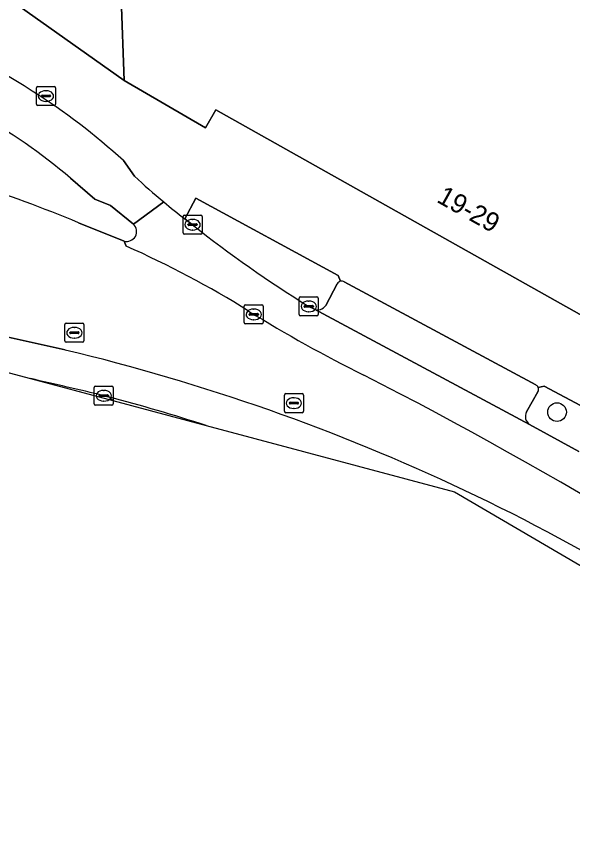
# Model space of a CAD drawing. Extents: x 161771 to 163125, y 382475 to 383179.
# Drawn here: x 161909.43 to 161938.58, y 382804.07 to 382847.18 of the extents above; entities that cross this region are included whole.
import ezdxf

# ---------------------------------------------------------------- set-up
doc = ezdxf.new("R2010")
doc.units = 0
for name, color, linetype in [('IMGEO_Boom', 7, 'Continuous'), ('IMGEO_Fietspad_gesloten', 7, 'Continuous'), ('IMGEO_Groenvoorziening', 7, 'Continuous'), ('IMGEO_Kolk', 7, 'Continuous'), ('IMGEO_Pand', 7, 'Continuous'), ('IMGEO_Pand_nummerreeks', 7, 'Continuous'), ('IMGEO_Parkeervlak_open', 7, 'Continuous'), ('IMGEO_Rijbaan_lokaal_gesloten', 7, 'Continuous'), ('IMGEO_Rijbaan_lokaal_open', 7, 'Continuous'), ('IMGEO_Rioolput', 7, 'Continuous'), ('IMGEO_Verkeerseiland_open', 7, 'Continuous'), ('IMGEO_Voetpad_open', 7, 'Continuous')]:
    doc.layers.add(name, color=color, linetype=linetype)

msp = doc.modelspace()

# ---------------------------------------------------------------- linework, layer by layer
at = {"layer": 'IMGEO_Boom'}
msp.add_circle((161937.763, 382826.46), 0.489, dxfattribs=at)
at = {"layer": 'IMGEO_Fietspad_gesloten'}
for points in [[(161915.615, 382838.816), (161915.031, 382839.631)], [(161912.258, 382838.707), (161913.543, 382837.611), (161914.36, 382837.276), (161915.553, 382836.298), (161917.147, 382837.468)]]:
    msp.add_lwpolyline(points, dxfattribs=at)
for centre, radius, start, end in [((161893.52, 382817.587), 30.654, 56.9204, 72.0344), ((161892.387, 382814.862), 33.56, 47.5667, 57.8391), ((161893.478, 382816.788), 28.864, 49.4108, 61.3259), ((161941.936, 382867.185), 38.699, 227.1448, 230.1664)]:
    msp.add_arc(centre, radius, start, end, dxfattribs=at)
at = {"layer": 'IMGEO_Groenvoorziening'}
for points in [[(161926.413, 382833.312), (161926.289, 382833.608), (161918.824, 382837.659), (161918.256, 382836.578)], [(161918.256, 382836.578), (161918.66, 382836.276)], [(161925.636, 382832.046), (161926.245, 382833.185)], [(161924.749, 382831.998), (161925.01, 382831.862)], [(161940.409, 382825.753), (161940.331, 382826.089), (161937.087, 382827.816), (161936.776, 382827.755)], [(161936.764, 382827.519), (161936.155, 382826.469)], [(161936.32, 382825.81), (161938.902, 382824.399)]]:
    msp.add_lwpolyline(points, dxfattribs=at)
for centre, radius, start, end in [((161956.208, 382883.247), 60.134, 231.36149, 238.45641), ((161926.482, 382833.046), 0.274, 104.5285, 149.6466), ((161925.219, 382832.307), 0.492, 244.8527, 327.9066), ((161936.525, 382827.649), 0.272, 331.33, 22.8483), ((161936.635, 382826.239), 0.532, 154.3803, 233.7331)]:
    msp.add_arc(centre, radius, start, end, dxfattribs=at)
at = {"layer": 'IMGEO_Kolk'}
for p, q in [((161910.471, 382842.589), (161910.471, 382843.441)), ((161910.546, 382843.515), (161911.398, 382843.515)), ((161910.959, 382843.295), (161910.984, 382843.295)), ((161911.472, 382843.441), (161911.472, 382842.589)), ((161910.73, 382843.009), (161910.73, 382843.021)), ((161911.168, 382842.972), (161910.77, 382842.972)), ((161910.773, 382843.058), (161911.171, 382843.058)), ((161910.982, 382842.735), (161910.957, 382842.735)), ((161911.214, 382843.021), (161911.214, 382843.009)), ((161911.398, 382842.515), (161910.546, 382842.515)), ((161918.159, 382835.85), (161918.159, 382836.702)), ((161918.234, 382836.776), (161919.086, 382836.776)), ((161919.16, 382836.702), (161919.16, 382835.85)), ((161918.418, 382836.27), (161918.418, 382836.282)), ((161918.856, 382836.233), (161918.458, 382836.233)), ((161918.461, 382836.319), (161918.859, 382836.319)), ((161918.647, 382836.556), (161918.672, 382836.556)), ((161918.902, 382836.282), (161918.902, 382836.27)), ((161918.67, 382835.996), (161918.645, 382835.996)), ((161919.086, 382835.776), (161918.234, 382835.776)), ((161924.248, 382831.572), (161924.248, 382832.424)), ((161924.323, 382832.498), (161925.175, 382832.498)), ((161925.249, 382832.424), (161925.249, 382831.572)), ((161924.507, 382831.992), (161924.507, 382832.004)), ((161924.945, 382831.955), (161924.547, 382831.955)), ((161924.55, 382832.041), (161924.948, 382832.041)), ((161924.736, 382832.278), (161924.761, 382832.278)), ((161924.991, 382832.004), (161924.991, 382831.992)), ((161925.175, 382831.498), (161924.323, 382831.498)), ((161924.759, 382831.718), (161924.734, 382831.718)), ((161913.502, 382826.893), (161913.502, 382827.745)), ((161913.577, 382827.819), (161914.429, 382827.819)), ((161913.99, 382827.599), (161914.015, 382827.599)), ((161914.503, 382827.745), (161914.503, 382826.893)), ((161913.761, 382827.313), (161913.761, 382827.325)), ((161914.199, 382827.276), (161913.801, 382827.276)), ((161913.804, 382827.362), (161914.202, 382827.362)), ((161914.245, 382827.325), (161914.245, 382827.313)), ((161914.429, 382826.819), (161913.577, 382826.819)), ((161914.013, 382827.039), (161913.988, 382827.039))]:
    msp.add_line(p, q, dxfattribs=at)
for points in [[(161910.471, 382842.589), (161910.471, 382843.441)], [(161910.546, 382843.515), (161911.398, 382843.515)], [(161911.472, 382843.441), (161911.472, 382842.589)], [(161911.398, 382842.515), (161910.546, 382842.515)], [(161918.159, 382835.85), (161918.159, 382836.702)], [(161918.234, 382836.776), (161919.086, 382836.776)], [(161919.16, 382836.702), (161919.16, 382835.85)], [(161919.086, 382835.776), (161918.234, 382835.776)], [(161924.248, 382831.572), (161924.248, 382832.424)], [(161924.323, 382832.498), (161925.175, 382832.498)], [(161925.249, 382832.424), (161925.249, 382831.572)], [(161925.175, 382831.498), (161924.323, 382831.498)], [(161913.502, 382826.893), (161913.502, 382827.745)], [(161913.577, 382827.819), (161914.429, 382827.819)], [(161914.503, 382827.745), (161914.503, 382826.893)], [(161914.429, 382826.819), (161913.577, 382826.819)]]:
    msp.add_lwpolyline(points, dxfattribs=at)
for centre, radius, start, end in [((161910.548, 382843.439), 0.0765, 91.552, 178.448), ((161910.548, 382843.439), 0.0765, 91.552, 178.448), ((161911.396, 382843.439), 0.0765, 1.552, 88.448), ((161911.396, 382843.439), 0.0765, 1.552, 88.448), ((161910.77, 382843.018), 0.0403, 85.8775, 175.7526), ((161910.767, 382843.008), 0.0366, 178.938, 274.7102), ((161911.171, 382843.015), 0.043, 264.8664, 352.4533), ((161911.175, 382843.02), 0.0386, 1.7309, 96.639), ((161910.548, 382842.591), 0.0765, 181.552, 268.448), ((161910.548, 382842.591), 0.0765, 181.552, 268.448), ((161911.396, 382842.591), 0.0765, 271.552, 358.448), ((161911.396, 382842.591), 0.0765, 271.552, 358.448), ((161918.236, 382836.7), 0.0765, 91.552, 178.448), ((161918.236, 382836.7), 0.0765, 91.552, 178.448), ((161919.084, 382836.7), 0.0765, 1.552, 88.448), ((161919.084, 382836.7), 0.0765, 1.552, 88.448), ((161918.458, 382836.279), 0.0403, 85.8775, 175.7526), ((161918.455, 382836.269), 0.0366, 178.938, 274.7102), ((161918.859, 382836.276), 0.043, 264.8664, 352.4533), ((161918.863, 382836.281), 0.0386, 1.7309, 96.639), ((161918.236, 382835.852), 0.0765, 181.552, 268.448), ((161918.236, 382835.852), 0.0765, 181.552, 268.448), ((161919.084, 382835.852), 0.0765, 271.552, 358.448), ((161919.084, 382835.852), 0.0765, 271.552, 358.448), ((161924.325, 382832.422), 0.0765, 91.552, 178.448), ((161924.325, 382832.422), 0.0765, 91.552, 178.448), ((161925.173, 382832.422), 0.0765, 1.552, 88.448), ((161925.173, 382832.422), 0.0765, 1.552, 88.448), ((161924.547, 382832.001), 0.0403, 85.8775, 175.7526), ((161924.544, 382831.991), 0.0366, 178.938, 274.7102), ((161924.948, 382831.998), 0.043, 264.8664, 352.4533), ((161924.952, 382832.003), 0.0386, 1.7309, 96.639), ((161924.325, 382831.574), 0.0765, 181.552, 268.448), ((161924.325, 382831.574), 0.0765, 181.552, 268.448), ((161925.173, 382831.574), 0.0765, 271.552, 358.448), ((161925.173, 382831.574), 0.0765, 271.552, 358.448), ((161913.579, 382827.743), 0.0765, 91.552, 178.448), ((161913.579, 382827.743), 0.0765, 91.552, 178.448), ((161914.427, 382827.743), 0.0765, 1.552, 88.448), ((161914.427, 382827.743), 0.0765, 1.552, 88.448), ((161913.801, 382827.322), 0.0403, 85.8775, 175.7526), ((161913.798, 382827.312), 0.0366, 178.938, 274.7102), ((161914.202, 382827.319), 0.043, 264.8664, 352.4533), ((161914.206, 382827.324), 0.0386, 1.7309, 96.639), ((161913.579, 382826.895), 0.0765, 181.552, 268.448), ((161913.579, 382826.895), 0.0765, 181.552, 268.448), ((161914.427, 382826.895), 0.0765, 271.552, 358.448), ((161914.427, 382826.895), 0.0765, 271.552, 358.448)]:
    msp.add_arc(centre, radius, start, end, dxfattribs=at)
for centre, major_axis, ratio, start_param, end_param in [((161910.958, 382843.015), (-0.387, 0.002), 0.722429, 4.712389, 7.853982), ((161910.983, 382843.015), (-0.39, 0.002), 0.717154, 1.570796, 4.712389), ((161918.646, 382836.276), (-0.387, 0.002), 0.722429, 4.712389, 7.853982), ((161918.671, 382836.276), (-0.39, 0.002), 0.717154, 1.570796, 4.712389), ((161924.735, 382831.998), (-0.387, 0.002), 0.722429, 4.712389, 7.853982), ((161924.76, 382831.998), (-0.39, 0.002), 0.717154, 1.570796, 4.712389), ((161913.989, 382827.319), (-0.387, 0.002), 0.722429, 4.712389, 7.853982), ((161914.014, 382827.319), (-0.39, 0.002), 0.717154, 1.570796, 4.712389)]:
    msp.add_ellipse(centre, major_axis=major_axis, ratio=ratio, start_param=start_param, end_param=end_param, dxfattribs=at)
at = {"layer": 'IMGEO_Pand'}
msp.add_lwpolyline([(161938.172, 382855.87), (161935.571, 382851.327), (161925.788, 382856.766), (161923.225, 382854.706), (161921.507, 382853.326), (161918.6, 382851.014), (161914.919, 382848.172), (161915.064, 382843.832), (161919.34, 382841.346), (161919.878, 382842.285), (161944.451, 382828.498), (161949.455, 382837.351), (161954.479, 382841.299), (161958.508, 382844.465)], close=True, dxfattribs=at)
at = {"layer": 'IMGEO_Parkeervlak_open'}
for points in [[(161936.655, 382827.886), (161926.611, 382833.288)], [(161926.245, 382833.185), (161925.636, 382832.046)], [(161925.01, 382831.862), (161936.32, 382825.81)], [(161936.155, 382826.469), (161936.764, 382827.519)], [(161914.482, 382827.063), (161919.366, 382825.762)]]:
    msp.add_lwpolyline(points, dxfattribs=at)
for centre, radius, start, end in [((161926.482, 382833.046), 0.274, 104.5285, 149.6466), ((161926.482, 382833.051), 0.27, 61.4009, 104.7767), ((161925.219, 382832.307), 0.492, 244.8527, 327.9066), ((161936.534, 382827.653), 0.263, 22.9147, 62.5404), ((161936.525, 382827.649), 0.272, 331.33, 22.8483), ((161889.903, 382734.077), 96.303, 72.18528, 75.35985), ((161914.05, 382826.763), 0.527, 34.7532, 68.4794), ((161936.635, 382826.239), 0.532, 154.3803, 233.7331)]:
    msp.add_arc(centre, radius, start, end, dxfattribs=at)
at = {"layer": 'IMGEO_Rijbaan_lokaal_gesloten'}
for points in [[(161917.147, 382837.468), (161915.553, 382836.298)], [(161918.66, 382836.276), (161918.256, 382836.578)], [(161915.067, 382835.419), (161915.18, 382835.151)], [(161911.985, 382829.713), (161908.827, 382830.418), (161897.919, 382832.611), (161894.604, 382833.278), (161894.438, 382831.588), (161898.722, 382831.263), (161910.159, 382828.215)], [(161938.902, 382824.399), (161936.32, 382825.81), (161925.01, 382831.862), (161924.749, 382831.998)], [(161914.003, 382827.319), (161914.243, 382827.253)], [(161919.366, 382825.762), (161932.388, 382822.292), (161951.892, 382810.876)]]:
    msp.add_lwpolyline(points, dxfattribs=at)
for centre, radius, start, end in [((161941.254, 382866.371), 37.637, 230.1697, 232.3345), ((161915.208, 382835.915), 0.515, 254.091, 48.0325), ((161956.208, 382883.247), 60.134, 231.36149, 238.45641), ((161894.407, 382788.165), 51.373, 58.0449, 66.1499), ((161959.575, 382893.012), 72.076, 238.20251, 243.6899), ((161886.934, 382724.948), 107.718, 52.91192, 76.55194), ((161858.06, 382596.106), 237.884, 76.39844, 77.34917), ((161822.897, 382623.343), 230.256, 54.43143, 62.94481), ((161889.903, 382734.077), 96.303, 72.18528, 75.35985)]:
    msp.add_arc(centre, radius, start, end, dxfattribs=at)
at = {"layer": 'IMGEO_Rijbaan_lokaal_open'}
for points in [[(161915.18, 382835.151), (161915.067, 382835.419), (161912.674, 382836.378)], [(161908.124, 382832.781), (161898.168, 382834.829), (161897.919, 382832.611), (161908.827, 382830.418), (161911.985, 382829.713)]]:
    msp.add_lwpolyline(points, dxfattribs=at)
for centre, radius, start, end in [((161884.089, 382767.932), 74.175, 67.33298, 76.62355), ((161894.407, 382788.165), 51.373, 58.0449, 66.1499), ((161959.575, 382893.012), 72.076, 238.20251, 243.6899), ((161886.934, 382724.948), 107.718, 52.91192, 76.55194), ((161822.897, 382623.343), 230.256, 54.43143, 62.94481)]:
    msp.add_arc(centre, radius, start, end, dxfattribs=at)
at = {"layer": 'IMGEO_Rioolput'}
for p, q in [((161921.363, 382831.152), (161921.363, 382832.004)), ((161921.438, 382832.078), (161922.29, 382832.078)), ((161922.364, 382832.004), (161922.364, 382831.152)), ((161921.622, 382831.572), (161921.622, 382831.584)), ((161922.06, 382831.535), (161921.662, 382831.535)), ((161921.665, 382831.621), (161922.063, 382831.621)), ((161921.851, 382831.858), (161921.876, 382831.858)), ((161922.106, 382831.584), (161922.106, 382831.572)), ((161911.961, 382830.19), (161911.961, 382831.042)), ((161912.036, 382831.116), (161912.888, 382831.116)), ((161912.962, 382831.042), (161912.962, 382830.19)), ((161922.29, 382831.078), (161921.438, 382831.078)), ((161921.874, 382831.298), (161921.849, 382831.298)), ((161912.22, 382830.61), (161912.22, 382830.622)), ((161912.263, 382830.659), (161912.661, 382830.659)), ((161912.449, 382830.896), (161912.474, 382830.896)), ((161912.704, 382830.622), (161912.704, 382830.61)), ((161912.658, 382830.573), (161912.26, 382830.573)), ((161912.472, 382830.336), (161912.447, 382830.336)), ((161912.888, 382830.116), (161912.036, 382830.116)), ((161923.47, 382826.503), (161923.47, 382827.355)), ((161923.545, 382827.429), (161924.397, 382827.429)), ((161923.958, 382827.209), (161923.983, 382827.209)), ((161924.471, 382827.355), (161924.471, 382826.503)), ((161923.729, 382826.923), (161923.729, 382826.935)), ((161924.167, 382826.886), (161923.769, 382826.886)), ((161923.772, 382826.972), (161924.17, 382826.972)), ((161924.213, 382826.935), (161924.213, 382826.923)), ((161924.397, 382826.429), (161923.545, 382826.429)), ((161923.981, 382826.649), (161923.956, 382826.649))]:
    msp.add_line(p, q, dxfattribs=at)
for points in [[(161921.363, 382831.152), (161921.363, 382832.004)], [(161921.438, 382832.078), (161922.29, 382832.078)], [(161922.364, 382832.004), (161922.364, 382831.152)], [(161911.961, 382830.19), (161911.961, 382831.042)], [(161912.036, 382831.116), (161912.888, 382831.116)], [(161912.962, 382831.042), (161912.962, 382830.19)], [(161922.29, 382831.078), (161921.438, 382831.078)], [(161912.888, 382830.116), (161912.036, 382830.116)], [(161923.47, 382826.503), (161923.47, 382827.355)], [(161923.545, 382827.429), (161924.397, 382827.429)], [(161924.471, 382827.355), (161924.471, 382826.503)], [(161924.397, 382826.429), (161923.545, 382826.429)]]:
    msp.add_lwpolyline(points, dxfattribs=at)
for centre, radius, start, end in [((161921.44, 382832.002), 0.0765, 91.552, 178.448), ((161921.44, 382832.002), 0.0765, 91.552, 178.448), ((161922.288, 382832.002), 0.0765, 1.552, 88.448), ((161922.288, 382832.002), 0.0765, 1.552, 88.448), ((161921.662, 382831.581), 0.0403, 85.8775, 175.7526), ((161921.659, 382831.571), 0.0366, 178.938, 274.7102), ((161922.063, 382831.578), 0.043, 264.8664, 352.4533), ((161922.067, 382831.583), 0.0386, 1.7309, 96.639), ((161912.038, 382831.04), 0.0765, 91.552, 178.448), ((161912.038, 382831.04), 0.0765, 91.552, 178.448), ((161912.886, 382831.04), 0.0765, 1.552, 88.448), ((161912.886, 382831.04), 0.0765, 1.552, 88.448), ((161921.44, 382831.154), 0.0765, 181.552, 268.448), ((161921.44, 382831.154), 0.0765, 181.552, 268.448), ((161922.288, 382831.154), 0.0765, 271.552, 358.448), ((161922.288, 382831.154), 0.0765, 271.552, 358.448), ((161912.26, 382830.619), 0.0403, 85.8775, 175.7526), ((161912.257, 382830.609), 0.0366, 178.938, 274.7102), ((161912.661, 382830.616), 0.043, 264.8664, 352.4533), ((161912.665, 382830.621), 0.0386, 1.7309, 96.639), ((161912.038, 382830.192), 0.0765, 181.552, 268.448), ((161912.038, 382830.192), 0.0765, 181.552, 268.448), ((161912.886, 382830.192), 0.0765, 271.552, 358.448), ((161912.886, 382830.192), 0.0765, 271.552, 358.448), ((161923.547, 382827.353), 0.0765, 91.552, 178.448), ((161923.547, 382827.353), 0.0765, 91.552, 178.448), ((161924.395, 382827.353), 0.0765, 1.552, 88.448), ((161924.395, 382827.353), 0.0765, 1.552, 88.448), ((161923.769, 382826.932), 0.0403, 85.8775, 175.7526), ((161923.766, 382826.922), 0.0366, 178.938, 274.7102), ((161924.17, 382826.929), 0.043, 264.8664, 352.4533), ((161924.174, 382826.934), 0.0386, 1.7309, 96.639), ((161923.547, 382826.505), 0.0765, 181.552, 268.448), ((161923.547, 382826.505), 0.0765, 181.552, 268.448), ((161924.395, 382826.505), 0.0765, 271.552, 358.448), ((161924.395, 382826.505), 0.0765, 271.552, 358.448)]:
    msp.add_arc(centre, radius, start, end, dxfattribs=at)
for centre, major_axis, ratio, start_param, end_param in [((161921.85, 382831.578), (-0.387, 0.002), 0.722429, 4.712389, 7.853982), ((161921.875, 382831.578), (-0.39, 0.002), 0.717154, 1.570796, 4.712389), ((161912.448, 382830.616), (-0.387, 0.002), 0.722429, 4.712389, 7.853982), ((161912.473, 382830.616), (-0.39, 0.002), 0.717154, 1.570796, 4.712389), ((161923.957, 382826.929), (-0.387, 0.002), 0.722429, 4.712389, 7.853982), ((161923.982, 382826.929), (-0.39, 0.002), 0.717154, 1.570796, 4.712389)]:
    msp.add_ellipse(centre, major_axis=major_axis, ratio=ratio, start_param=start_param, end_param=end_param, dxfattribs=at)
at = {"layer": 'IMGEO_Verkeerseiland_open'}
for points in [[(161915.553, 382836.298), (161914.36, 382837.276), (161913.543, 382837.611), (161912.258, 382838.707)], [(161912.674, 382836.378), (161915.067, 382835.419)]]:
    msp.add_lwpolyline(points, dxfattribs=at)
for centre, radius, start, end in [((161893.478, 382816.788), 28.864, 49.4108, 61.3259), ((161884.089, 382767.932), 74.175, 67.33298, 76.62355), ((161915.208, 382835.915), 0.515, 254.091, 48.0325)]:
    msp.add_arc(centre, radius, start, end, dxfattribs=at)
at = {"layer": 'IMGEO_Voetpad_open'}
for points in [[(161908.806, 382849.443), (161908.423, 382848.544), (161915.064, 382843.832), (161914.919, 382848.172), (161918.6, 382851.014), (161919.975, 382853.379), (161920.916, 382852.897), (161922.304, 382855.223), (161923.225, 382854.706), (161925.788, 382856.766), (161930.217, 382860.359), (161934.42, 382863.739), (161937.25, 382865.994), (161937.488, 382866.185)], [(161919.878, 382842.285), (161919.34, 382841.346), (161915.064, 382843.832), (161908.423, 382848.544), (161907.047, 382848.97), (161903.828, 382850.026), (161902.529, 382850.444), (161902.759, 382851.432)], [(162013.278, 382773.96), (162016.666, 382777.602), (162014.703, 382779.815), (162012.95, 382779.713), (162008.994, 382783.177), (162008.9, 382783.259), (162007.486, 382781.832), (162003.337, 382785.143), (162000, 382787.854), (161997.776, 382789.66), (161999.165, 382791.37), (161993.375, 382796.093), (161993.267, 382795.96), (161979.452, 382807.183), (161979.326, 382806.979), (161978.893, 382807.245), (161972.332, 382811.265), (161965.52, 382815.44), (161962.509, 382817.293), (161953.171, 382822.43), (161943.963, 382827.66), (161944.451, 382828.498), (161919.878, 382842.285)], [(161915.031, 382839.631), (161915.615, 382838.816)], [(161918.256, 382836.578), (161918.824, 382837.659), (161926.289, 382833.608), (161926.413, 382833.312)], [(161926.611, 382833.288), (161936.655, 382827.886)], [(161910.159, 382828.215), (161914.482, 382827.063)], [(161936.776, 382827.755), (161937.087, 382827.816), (161940.331, 382826.089), (161940.409, 382825.753)], [(161914.243, 382827.253), (161914.003, 382827.319)]]:
    msp.add_lwpolyline(points, dxfattribs=at)
for centre, radius, start, end in [((161893.52, 382817.587), 30.654, 56.9204, 72.0344), ((161892.387, 382814.862), 33.56, 47.5667, 57.8391), ((161941.936, 382867.185), 38.699, 227.1448, 230.1664), ((161941.254, 382866.371), 37.637, 230.1697, 232.3345), ((161926.482, 382833.051), 0.27, 61.4009, 104.7767), ((161858.06, 382596.106), 237.884, 76.39844, 77.34917), ((161936.534, 382827.653), 0.263, 22.9147, 62.5404), ((161914.05, 382826.763), 0.527, 34.7532, 68.4794)]:
    msp.add_arc(centre, radius, start, end, dxfattribs=at)

# ---------------------------------------------------------------- texts
at = {"layer": 'IMGEO_Pand_nummerreeks'}
msp.add_text('19-29', height=1, rotation=330.8021, dxfattribs=at).set_placement((161931.405, 382837.489))

doc.saveas('drawing.dxf')
